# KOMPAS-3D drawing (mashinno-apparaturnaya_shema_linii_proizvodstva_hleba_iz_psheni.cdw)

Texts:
  ОУП-02068108-260601-96-2010
  Машинно-аппаратурная схема  линии производства хлеба  из пшеничной муки
  Игорь
  Мука
  Вода
  Соль
  Хлеб
  Пар
  Конденсат
  Дрожжи
  Р-р соли
  Машинно-аппаратурная схема
  линии производства хлеба
  из пшеничной муки
  Саранов И.А.
  Рязанов А.Н.
  УП-02068108-260601-2010-
Dimensions and other numbers on the sheet: 1; 2; 3; 4; 5; 6; 7; 8; 9; 10; 11; 12; 13; 14; 15; 16; 17; 18; 19; 20; 21; 22; 23; 24; 25; 26; 27; 0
